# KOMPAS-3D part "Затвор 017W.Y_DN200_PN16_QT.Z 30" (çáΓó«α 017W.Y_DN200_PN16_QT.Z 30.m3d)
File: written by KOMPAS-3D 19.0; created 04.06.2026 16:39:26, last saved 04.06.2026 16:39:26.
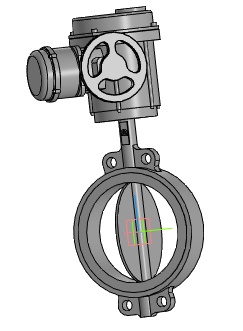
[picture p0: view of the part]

Document properties: Автор: Энергия; Полное имя файла: ..\..\..\3d для проектировщиков\017W разные\x.x Тип 017W.Y(S) Затвор дисковый поворотный межфланцевый\Затвор 017W.Y(S)_DN32-DN450_QT.Z\Затвор 017W.Y_DN200_PN16_QT.Z 30.a3d

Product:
- Part/product: Затвор 017W.Y_DN200_PN16_QT.Z 30
    Масса: 57.6031

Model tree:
1. Операция без истории:1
